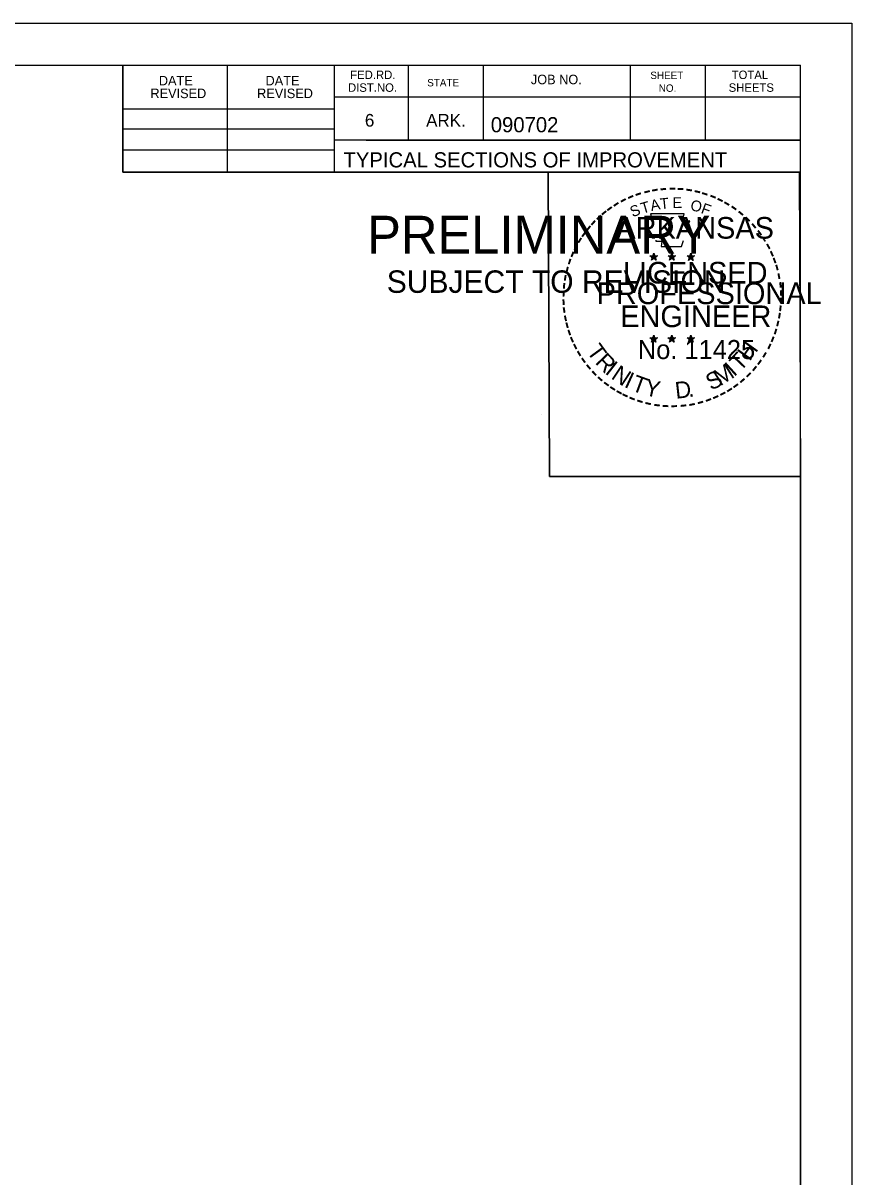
# Model space of a CAD drawing. Extents: x 1371763 to 1372860, y 385599 to 385872.
# Drawn here: x 1371891.7 to 1371930, y 385651.9 to 385705.3 of the extents above; entities that cross this region are included whole.
import ezdxf

# ---------------------------------------------------------------- set-up
doc = ezdxf.new("R2010")
doc.units = 0
for name, color, linetype in [('R_Border', 7, 'Continuous'), ('R_Border PE', 7, 'Continuous'), ('R_Border Prem', 7, 'Continuous'), ('R_No Plot', 7, 'Continuous')]:
    doc.layers.add(name, color=color, linetype=linetype)

msp = doc.modelspace()

# ---------------------------------------------------------------- linework, layer by layer
at = {"layer": 'R_Border'}
for p, q in [((1371769.555, 385703.307), (1371927.645, 385703.307)), ((1371896.325, 385698.367), (1371896.325, 385703.307)), ((1371901.165, 385698.367), (1371901.165, 385703.307)), ((1371906.095, 385703.307), (1371906.095, 385698.367)), ((1371909.515, 385703.307), (1371909.515, 385699.837)), ((1371912.985, 385703.307), (1371912.985, 385699.837)), ((1371919.775, 385703.307), (1371919.775, 385699.837)), ((1371923.245, 385703.307), (1371923.245, 385699.837)), ((1371927.645, 385600.577), (1371927.645, 385703.307)), ((1371927.645, 385701.837), (1371906.095, 385701.837)), ((1371927.645, 385701.847), (1371927.645, 385701.847)), ((1371896.325, 385701.297), (1371906.095, 385701.297)), ((1371896.325, 385700.367), (1371906.095, 385700.367)), ((1371927.645, 385699.837), (1371906.095, 385699.837)), ((1371907.575, 385699.837), (1371927.645, 385699.837)), ((1371896.325, 385699.397), (1371906.095, 385699.397)), ((1371927.645, 385698.367), (1371896.325, 385698.367))]:
    msp.add_line(p, q, dxfattribs=at)
at = {"layer": 'R_Border PE'}
for p, q in [((1371920.687, 385694.494), (1371920.862, 385694.439)), ((1371920.687, 385694.494), (1371920.814, 385694.472)), ((1371920.687, 385694.494), (1371920.806, 385694.433)), ((1371920.754, 385694.29), (1371920.862, 385694.439)), ((1371920.754, 385694.29), (1371920.817, 385694.412)), ((1371920.754, 385694.29), (1371920.861, 385694.399)), ((1371920.862, 385694.621), (1371920.841, 385694.495)), ((1371920.968, 385694.29), (1371920.861, 385694.397)), ((1371920.862, 385694.439), (1371920.862, 385694.621)), ((1371920.862, 385694.621), (1371920.886, 385694.496)), ((1371921.035, 385694.494), (1371920.862, 385694.439)), ((1371920.968, 385694.29), (1371920.862, 385694.439)), ((1371921.035, 385694.494), (1371920.892, 385694.47)), ((1371920.968, 385694.29), (1371920.9, 385694.436)), ((1371921.035, 385694.494), (1371920.933, 385694.443)), ((1371921.522, 385694.494), (1371921.697, 385694.439)), ((1371921.522, 385694.494), (1371921.649, 385694.472)), ((1371921.522, 385694.494), (1371921.641, 385694.433)), ((1371921.589, 385694.29), (1371921.697, 385694.439)), ((1371921.589, 385694.29), (1371921.652, 385694.412)), ((1371921.589, 385694.29), (1371921.696, 385694.399)), ((1371921.697, 385694.621), (1371921.676, 385694.495)), ((1371921.803, 385694.29), (1371921.696, 385694.397)), ((1371921.697, 385694.439), (1371921.697, 385694.621)), ((1371921.697, 385694.621), (1371921.721, 385694.496)), ((1371921.87, 385694.494), (1371921.697, 385694.439)), ((1371921.803, 385694.29), (1371921.697, 385694.439)), ((1371921.87, 385694.494), (1371921.727, 385694.47)), ((1371921.803, 385694.29), (1371921.735, 385694.436)), ((1371921.87, 385694.494), (1371921.768, 385694.443)), ((1371922.404, 385694.488), (1371922.579, 385694.433)), ((1371922.404, 385694.488), (1371922.531, 385694.466)), ((1371922.404, 385694.488), (1371922.523, 385694.427)), ((1371922.471, 385694.284), (1371922.579, 385694.433)), ((1371922.471, 385694.284), (1371922.534, 385694.406)), ((1371922.471, 385694.284), (1371922.578, 385694.393)), ((1371922.579, 385694.615), (1371922.558, 385694.489)), ((1371922.685, 385694.284), (1371922.578, 385694.391)), ((1371922.579, 385694.433), (1371922.579, 385694.615)), ((1371922.579, 385694.615), (1371922.603, 385694.49)), ((1371922.752, 385694.488), (1371922.579, 385694.433)), ((1371922.685, 385694.284), (1371922.579, 385694.433)), ((1371922.752, 385694.488), (1371922.609, 385694.464)), ((1371922.685, 385694.284), (1371922.617, 385694.43)), ((1371922.752, 385694.488), (1371922.65, 385694.437)), ((1371920.685, 385690.708), (1371920.86, 385690.652)), ((1371920.685, 385690.708), (1371920.812, 385690.685)), ((1371920.685, 385690.708), (1371920.804, 385690.647)), ((1371920.752, 385690.504), (1371920.86, 385690.652)), ((1371920.752, 385690.504), (1371920.815, 385690.626)), ((1371920.752, 385690.504), (1371920.859, 385690.612)), ((1371920.86, 385690.835), (1371920.839, 385690.709)), ((1371920.966, 385690.504), (1371920.859, 385690.611)), ((1371920.86, 385690.652), (1371920.86, 385690.835)), ((1371920.86, 385690.835), (1371920.884, 385690.71)), ((1371921.033, 385690.708), (1371920.86, 385690.652)), ((1371920.966, 385690.504), (1371920.86, 385690.652)), ((1371921.033, 385690.708), (1371920.89, 385690.683)), ((1371920.966, 385690.504), (1371920.898, 385690.649)), ((1371921.033, 385690.708), (1371920.931, 385690.657)), ((1371921.52, 385690.708), (1371921.694, 385690.652)), ((1371921.52, 385690.708), (1371921.646, 385690.685)), ((1371921.52, 385690.708), (1371921.638, 385690.647)), ((1371921.586, 385690.504), (1371921.694, 385690.652)), ((1371921.586, 385690.504), (1371921.649, 385690.626)), ((1371921.586, 385690.504), (1371921.693, 385690.612)), ((1371921.694, 385690.835), (1371921.674, 385690.709)), ((1371921.801, 385690.504), (1371921.693, 385690.611)), ((1371921.694, 385690.652), (1371921.694, 385690.835)), ((1371921.694, 385690.835), (1371921.719, 385690.71)), ((1371921.868, 385690.708), (1371921.694, 385690.652)), ((1371921.801, 385690.504), (1371921.694, 385690.652)), ((1371921.868, 385690.708), (1371921.725, 385690.683)), ((1371921.801, 385690.504), (1371921.732, 385690.649)), ((1371921.868, 385690.708), (1371921.766, 385690.657)), ((1371922.403, 385690.703), (1371922.578, 385690.647)), ((1371922.403, 385690.703), (1371922.53, 385690.68)), ((1371922.403, 385690.703), (1371922.522, 385690.642)), ((1371922.47, 385690.499), (1371922.578, 385690.647)), ((1371922.47, 385690.499), (1371922.533, 385690.621)), ((1371922.47, 385690.499), (1371922.577, 385690.607)), ((1371922.578, 385690.83), (1371922.557, 385690.704)), ((1371922.684, 385690.499), (1371922.577, 385690.606)), ((1371922.578, 385690.647), (1371922.578, 385690.83)), ((1371922.578, 385690.83), (1371922.602, 385690.705)), ((1371922.751, 385690.703), (1371922.578, 385690.647)), ((1371922.684, 385690.499), (1371922.578, 385690.647)), ((1371922.751, 385690.703), (1371922.608, 385690.678)), ((1371922.684, 385690.499), (1371922.616, 385690.644)), ((1371922.751, 385690.703), (1371922.649, 385690.652))]:
    msp.add_line(p, q, dxfattribs=at)
for points in [[(1371920.708, 385696.433), (1371920.842, 385696.02)], [(1371922.463, 385695.972), (1371922.534, 385696.114), (1371922.192, 385696.102), (1371922.266, 385696.433), (1371920.708, 385696.433)], [(1371920.954, 385695.222), (1371920.954, 385695.178), (1371921.235, 385695.169), (1371921.208, 385694.932), (1371922.143, 385694.932), (1371922.244, 385695.2)], [(1371920.862, 385694.621), (1371920.968, 385694.29), (1371920.687, 385694.494), (1371921.035, 385694.494), (1371920.754, 385694.29), (1371920.862, 385694.621)], [(1371921.697, 385694.621), (1371921.803, 385694.29), (1371921.522, 385694.494), (1371921.87, 385694.494), (1371921.589, 385694.29), (1371921.697, 385694.621)], [(1371922.579, 385694.615), (1371922.685, 385694.284), (1371922.404, 385694.488), (1371922.752, 385694.488), (1371922.471, 385694.284), (1371922.579, 385694.615)], [(1371920.86, 385690.835), (1371920.966, 385690.504), (1371920.685, 385690.708), (1371921.033, 385690.708), (1371920.752, 385690.504), (1371920.86, 385690.835)], [(1371921.694, 385690.835), (1371921.801, 385690.504), (1371921.52, 385690.708), (1371921.868, 385690.708), (1371921.586, 385690.504), (1371921.694, 385690.835)], [(1371922.578, 385690.83), (1371922.684, 385690.499), (1371922.403, 385690.703), (1371922.751, 385690.703), (1371922.47, 385690.499), (1371922.578, 385690.83)]]:
    msp.add_lwpolyline(points, dxfattribs=at)
for centre, radius in [((1371920.861, 385694.438), 0.0861), ((1371920.861, 385694.438), 0.0723), ((1371920.861, 385694.438), 0.0579), ((1371920.861, 385694.438), 0.0495), ((1371920.861, 385694.438), 0.0374), ((1371920.861, 385694.438), 0.0248), ((1371920.861, 385694.438), 0.0148), ((1371921.696, 385694.438), 0.0861), ((1371921.696, 385694.438), 0.0723), ((1371921.696, 385694.438), 0.0579), ((1371921.696, 385694.438), 0.0495), ((1371921.696, 385694.438), 0.0374), ((1371921.696, 385694.438), 0.0248), ((1371921.696, 385694.438), 0.0148), ((1371922.578, 385694.432), 0.0861), ((1371922.578, 385694.432), 0.0723), ((1371922.578, 385694.432), 0.0579), ((1371922.578, 385694.432), 0.0495), ((1371922.578, 385694.432), 0.0374), ((1371922.578, 385694.432), 0.0248), ((1371922.578, 385694.432), 0.0148), ((1371920.859, 385690.652), 0.0861), ((1371920.859, 385690.652), 0.0723), ((1371920.859, 385690.652), 0.0579), ((1371920.859, 385690.652), 0.0495), ((1371920.859, 385690.652), 0.0374), ((1371920.859, 385690.652), 0.0248), ((1371920.859, 385690.652), 0.0148), ((1371921.694, 385690.652), 0.0861), ((1371921.694, 385690.652), 0.0723), ((1371921.694, 385690.652), 0.0579), ((1371921.694, 385690.652), 0.0495), ((1371921.694, 385690.652), 0.0374), ((1371921.694, 385690.652), 0.0248), ((1371921.694, 385690.652), 0.0148), ((1371922.577, 385690.647), 0.0861), ((1371922.577, 385690.647), 0.0723), ((1371922.577, 385690.647), 0.0579), ((1371922.577, 385690.647), 0.0495), ((1371922.577, 385690.647), 0.0374), ((1371922.577, 385690.647), 0.0248), ((1371922.577, 385690.647), 0.0148)]:
    msp.add_circle(centre, radius, dxfattribs=at)
at = {"layer": 'R_No Plot'}
for p, q in [((1371763.354, 385705.254), (1371930.021, 385705.254)), ((1371915.662, 385687.139), (1371915.662, 385687.139))]:
    msp.add_line(p, q, dxfattribs=at)
for points in [[(1371763.351, 385705.254), (1371930.021, 385705.254), (1371930.021, 385598.585), (1371763.351, 385598.585)], [(1371886.515, 385703.307), (1371896.325, 385703.307), (1371896.325, 385698.367), (1371904.381, 385698.367), (1371915.98, 385698.367), (1371916.041, 385684.288), (1371927.645, 385684.288), (1371927.645, 385600.577), (1371769.555, 385600.577), (1371769.555, 385703.307)], [(1371915.98, 385698.367), (1371927.584, 385698.367), (1371927.645, 385684.288), (1371916.041, 385684.288)]]:
    msp.add_lwpolyline(points, close=True, dxfattribs=at)

# ---------------------------------------------------------------- texts
at = {"layer": 'R_Border'}
for s, height, p in [('DATE', 0.4396, (1371897.994, 385702.375)), ('DATE', 0.4396, (1371902.924, 385702.375)), ('FED.RD.', 0.391, (1371906.835, 385702.667)), ('STATE', 0.342, (1371910.395, 385702.327)), ('JOB NO.', 0.4396, (1371915.185, 385702.427)), ('SHEET', 0.342, (1371920.705, 385702.667)), ('TOTAL', 0.391, (1371924.465, 385702.667)), ('REVISED', 0.4396, (1371897.604, 385701.785)), ('REVISED', 0.4396, (1371902.534, 385701.785)), ('DIST.NO.', 0.391, (1371906.735, 385702.077)), ('NO.', 0.342, (1371921.095, 385702.077)), ('SHEETS', 0.391, (1371924.325, 385702.077)), ('6', 0.586, (1371907.515, 385700.467)), ('ARK.', 0.5861, (1371910.345, 385700.467)), ('090702', 0.7, (1371913.333, 385700.206)), ('TYPICAL SECTIONS OF IMPROVEMENT', 0.7, (1371906.526, 385698.582))]:
    msp.add_text(s, height=height, dxfattribs=at).set_placement(p)
at = {"layer": 'R_Border PE'}
for s, height, rotation, p in [('-', 0.8, 19.1761, (1371920.081, 385696.997)), ('-', 0.8, 13.6302, (1371920.456, 385697.117)), ('-', 0.8, 10.2193, (1371920.795, 385697.198)), ('-', 0.8, 5.8968, (1371921.16, 385697.253)), ('-', 0.8, 0.1862, (1371921.546, 385697.289)), ('-', 0.8, 357.743, (1371921.907, 385697.283)), ('-', 0.8, 352.1617, (1371922.279, 385697.255)), ('-', 0.8, 347.2049, (1371922.639, 385697.198)), ('-', 0.8, 342.3362, (1371922.956, 385697.12)), ('-', 0.8, 337.8551, (1371923.324, 385697.009)), ('-', 0.8, 36.2317, (1371918.86, 385696.321)), ('-', 0.8, 34.0636, (1371919.149, 385696.519)), ('-', 0.8, 28.7918, (1371919.448, 385696.704)), ('-', 0.8, 24.3072, (1371919.764, 385696.862)), ('S', 0.5, 21.594, (1371919.885, 385696.272)), ('T', 0.5, 16.4036, (1371920.342, 385696.438)), ('A', 0.5, 11.2132, (1371920.755, 385696.563)), ('T', 0.5, 6.0228, (1371921.179, 385696.646)), ('E', 0.5, 0.8323, (1371921.732, 385696.701)), ('O', 0.5, 350.4515, (1371922.534, 385696.596)), ('F', 0.5, 340.0707, (1371923.011, 385696.482)), ('-', 0.8, 334.1211, (1371923.639, 385696.873)), ('-', 0.8, 329.6409, (1371923.929, 385696.732)), ('-', 0.8, 325.8627, (1371924.25, 385696.551)), ('-', 0.8, 42.9622, (1371918.406, 385695.924)), ('-', 0.8, 38.9507, (1371918.622, 385696.132)), ('-', 0.8, 320.5297, (1371924.555, 385696.338)), ('-', 0.8, 315.5786, (1371924.855, 385696.094)), ('-', 0.8, 50.6142, (1371917.98, 385695.442)), ('-', 0.8, 48.4231, (1371918.182, 385695.685)), ('-', 0.8, 309.8797, (1371925.139, 385695.819)), ('-', 0.8, 58.0706, (1371917.611, 385694.895)), ('-', 0.8, 54.2325, (1371917.774, 385695.158)), ('-', 0.8, 306.6522, (1371925.402, 385695.518)), ('-', 0.7, 303.6753, (1371925.645, 385695.234)), ('-', 0.8, 67.7743, (1371917.325, 385694.282)), ('-', 0.8, 62.8713, (1371917.455, 385694.588)), ('-', 0.8, 299.6684, (1371925.804, 385694.931)), ('-', 0.8, 294.6628, (1371925.966, 385694.625)), ('-', 0.8, 72.3945, (1371917.216, 385693.967)), ('-', 0.8, 290.5728, (1371926.095, 385694.336)), ('-', 0.8, 81.2013, (1371917.051, 385693.254)), ('-', 0.8, 75.461, (1371917.117, 385693.61)), ('-', 0.8, 285.1233, (1371926.212, 385694.046)), ('-', 0.8, 280.5493, (1371926.312, 385693.675)), ('-', 0.8, 85.1863, (1371917.013, 385692.908)), ('-', 0.8, 276.5962, (1371926.393, 385693.291)), ('-', 0.8, 89.0622, (1371917.001, 385692.558)), ('-', 0.8, 274.3301, (1371926.423, 385692.93)), ('-', 0.8, 269.9407, (1371926.44, 385692.614)), ('-', 0.8, 94.1959, (1371917.018, 385692.195)), ('-', 0.8, 98.9479, (1371917.054, 385691.862)), ('-', 0.8, 263.5172, (1371926.43, 385692.281)), ('-', 0.8, 101.7149, (1371917.122, 385691.495)), ('-', 0.8, 255.7626, (1371926.34, 385691.615)), ('-', 0.8, 260.9953, (1371926.395, 385691.954)), ('-', 0.8, 105.4578, (1371917.203, 385691.198)), ('-', 0.8, 109.0874, (1371917.31, 385690.882)), ('-', 0.8, 252.8681, (1371926.249, 385691.255)), ('-', 0.8, 114.0643, (1371917.437, 385690.584)), ('-', 0.8, 115.7289, (1371917.59, 385690.275)), ('T', 0.77, 306.0406, (1371917.739, 385690.071)), ('H', 0.77, 54.6088, (1371925.299, 385689.589)), ('-', 0.8, 244.6197, (1371926.007, 385690.604)), ('-', 0.8, 247.8887, (1371926.138, 385690.919)), ('-', 0.8, 120.4471, (1371917.768, 385689.982)), ('R', 0.77, 314.005, (1371918.121, 385689.547)), ('T', 0.77, 46.6444, (1371924.855, 385689.118)), ('-', 0.8, 239.0712, (1371925.81, 385690.228)), ('-', 0.8, 125.8934, (1371917.97, 385689.702)), ('-', 0.8, 130.7181, (1371918.201, 385689.426)), ('I', 0.77, 321.9694, (1371918.571, 385689.081)), ('N', 0.77, 326.5002, (1371918.854, 385688.846)), ('M', 0.77, 32.6563, (1371923.932, 385688.455)), ('I', 0.77, 42.1136, (1371924.574, 385688.879)), ('-', 0.8, 231.2538, (1371925.394, 385689.619)), ('-', 0.8, 233.8452, (1371925.609, 385689.902)), ('-', 0.8, 134.2238, (1371918.459, 385689.153)), ('-', 0.8, 138.9338, (1371918.722, 385688.921)), ('I', 0.77, 335.3603, (1371919.459, 385688.453)), ('T', 0.77, 339.8912, (1371919.789, 385688.289)), ('Y', 0.77, 347.8556, (1371920.398, 385688.066)), ('S', 0.77, 26.9312, (1371923.512, 385688.252)), ('-', 0.8, 221.0851, (1371924.893, 385689.082)), ('-', 0.8, 225.7653, (1371925.154, 385689.337)), ('-', 0.8, 144.6463, (1371919, 385688.718)), ('-', 0.8, 148.0898, (1371919.28, 385688.533)), ('-', 0.8, 151.5704, (1371919.57, 385688.37)), ('D', 0.77, 6.3969, (1371921.89, 385687.887)), ('-', 0.8, 212.2491, (1371924.352, 385688.653)), ('-', 0.8, 215.7363, (1371924.619, 385688.846)), ('-', 0.8, 154.6002, (1371919.831, 385688.247)), ('-', 0.8, 158.5612, (1371920.143, 385688.12)), ('-', 0.8, 162.7983, (1371920.486, 385688.013)), ('-', 0.8, 167.5555, (1371920.844, 385687.931)), ('.', 0.77, 13.7642, (1371922.486, 385687.951)), ('-', 0.8, 195.4743, (1371923.113, 385688.063)), ('-', 0.8, 200.7184, (1371923.451, 385688.184)), ('-', 0.8, 204.2516, (1371923.761, 385688.32)), ('-', 0.8, 207.3568, (1371924.073, 385688.48)), ('-', 0.8, 173.1155, (1371921.23, 385687.876)), ('-', 0.8, 176.5183, (1371921.604, 385687.85)), ('-', 0.8, 181.5918, (1371921.976, 385687.859)), ('-', 0.8, 185.8167, (1371922.38, 385687.897)), ('-', 0.8, 191.2858, (1371922.748, 385687.963))]:
    msp.add_text(s, height=height, rotation=rotation, dxfattribs=at).set_placement(p)
for s, height, p in [('ARKANSAS', 1, (1371919.134, 385695.289)), ('LICENSED', 1, (1371919.433, 385693.215)), ('DWB', 0.005, (1371920.855, 385694.436)), ('DWB', 0.005, (1371921.69, 385694.436)), ('DWB', 0.005, (1371922.572, 385694.431)), ('PROFESSIONAL', 1, (1371918.221, 385692.263)), ('ENGINEER', 1, (1371919.314, 385691.2)), ('No. 11425', 0.8785, (1371920.128, 385689.725)), ('DWB', 0.005, (1371920.853, 385690.65)), ('DWB', 0.005, (1371921.688, 385690.65)), ('DWB', 0.005, (1371922.571, 385690.645))]:
    msp.add_text(s, height=height, dxfattribs=at).set_placement(p)
at = {"layer": 'R_Border Prem'}
for s, height, p in [('PRELIMINARY', 1.75, (1371907.62, 385694.598)), ('DWB', 0.005, (1371907.994, 385695.523)), ('SUBJECT TO REVISION', 1.03756, (1371908.525, 385692.784))]:
    msp.add_text(s, height=height, dxfattribs=at).set_placement(p)

doc.saveas('drawing.dxf')
